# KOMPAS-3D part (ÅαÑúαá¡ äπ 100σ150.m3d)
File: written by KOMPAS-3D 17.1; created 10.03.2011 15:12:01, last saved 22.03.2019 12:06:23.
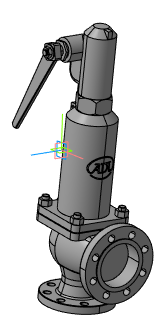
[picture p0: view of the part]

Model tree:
1. Плоскость XY
2. Плоскость ZX
3. Плоскость ZY
4. Ось X
5. Ось Y
6. Ось Z
7. Начало координат
8. Операция без истории:2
